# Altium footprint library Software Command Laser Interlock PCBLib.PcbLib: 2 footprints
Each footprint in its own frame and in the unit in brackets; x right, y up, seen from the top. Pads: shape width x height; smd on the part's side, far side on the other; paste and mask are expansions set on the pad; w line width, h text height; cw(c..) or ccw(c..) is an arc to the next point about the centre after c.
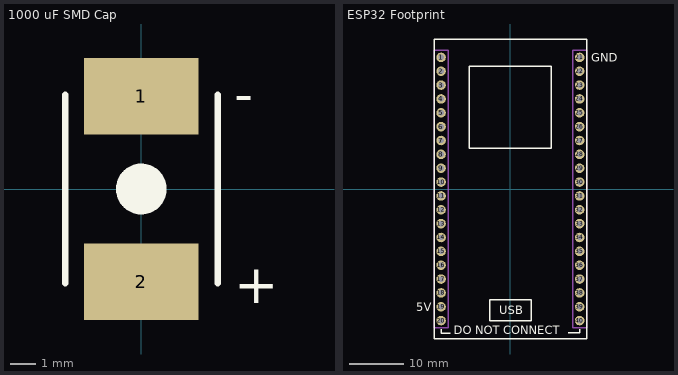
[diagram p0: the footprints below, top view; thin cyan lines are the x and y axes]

## 1000 uF SMD Cap [mm]
pads (2):
  rect 4.5x3 smd: 1(0,3.65) 2(0,-3.65)
Top Overlay:
  circle w1: c0,0 r0.5
  lines w0.254: -3,-3.7 -3,3.7 ; 3,-3.7 3,3.7
  text "+" at 3.654,-4.5 h1.52
  text "-" at 3.654,2.992 h1.52
Mechanical 1:
  text "'.Designator'" at 3.654,0.262 h1.52

## ESP32 Footprint [mm]
pads (40):
  round 1.75 hole 1: 1(-12.7,24.13) 2(-12.7,21.59) 3(-12.7,19.05) 4(-12.7,16.51) 5(-12.7,13.97) 6(-12.7,11.43) 7(-12.7,8.89) 8(-12.7,6.35) 9(-12.7,3.81) 10(-12.7,1.27) 11(-12.7,-1.27) 12(-12.7,-3.81) 13(-12.7,-6.35) 14(-12.7,-8.89) 15(-12.7,-11.43) 16(-12.7,-13.97) 17(-12.7,-16.51) 18(-12.7,-19.05) 19(-12.7,-21.59) 20(-12.7,-24.13) 21(12.7,24.13) 22(12.7,21.59) 23(12.7,19.05) 24(12.7,16.51) 25(12.7,13.97) 26(12.7,11.43) 27(12.7,8.89) 28(12.7,6.35) 29(12.7,3.81) 30(12.7,1.27) 31(12.7,-1.27) 32(12.7,-3.81) 33(12.7,-6.35) 34(12.7,-8.89) 35(12.7,-11.43) 36(12.7,-13.97) 37(12.7,-16.51) 38(12.7,-19.05) 39(12.7,-21.59) 40(12.7,-24.13)
Top Overlay:
  lines w0.254: -12.7,-25.7 -12.7,-26.4 -11,-26.4 ; 10.6,-26.4 12.7,-26.4 12.7,-25.7 ; -14,-27.5 14,-27.5 14,27.5 -14,27.5 -14,-27.5 ; -7.5,7.5 7.5,7.5 7.5,22.5 -7.5,22.5 -7.5,7.5 ; -3.81,-24.13 3.81,-24.13 3.81,-20.32 -3.81,-20.32 -3.81,-24.13
  text "5V" at -17.246,-22.446 h1.52
  text "GND" at 14.854,23.354 h1.52
  text "." at -9.8,25.9 h1.52
  text "DO NOT CONNECT" at -10.411,-26.646 h1.52
  text "USB" at -2.031,-22.946 h1.52
Mechanical 1:
  lines w0.254: -13.97,-25.4 -11.43,-25.4 -11.43,25.4 -13.97,25.4 -13.97,-25.4 ; 11.43,-25.4 13.97,-25.4 13.97,25.4 11.43,25.4 11.43,-25.4
  text "'.Designator'" at -13.716,28.702 h1.52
